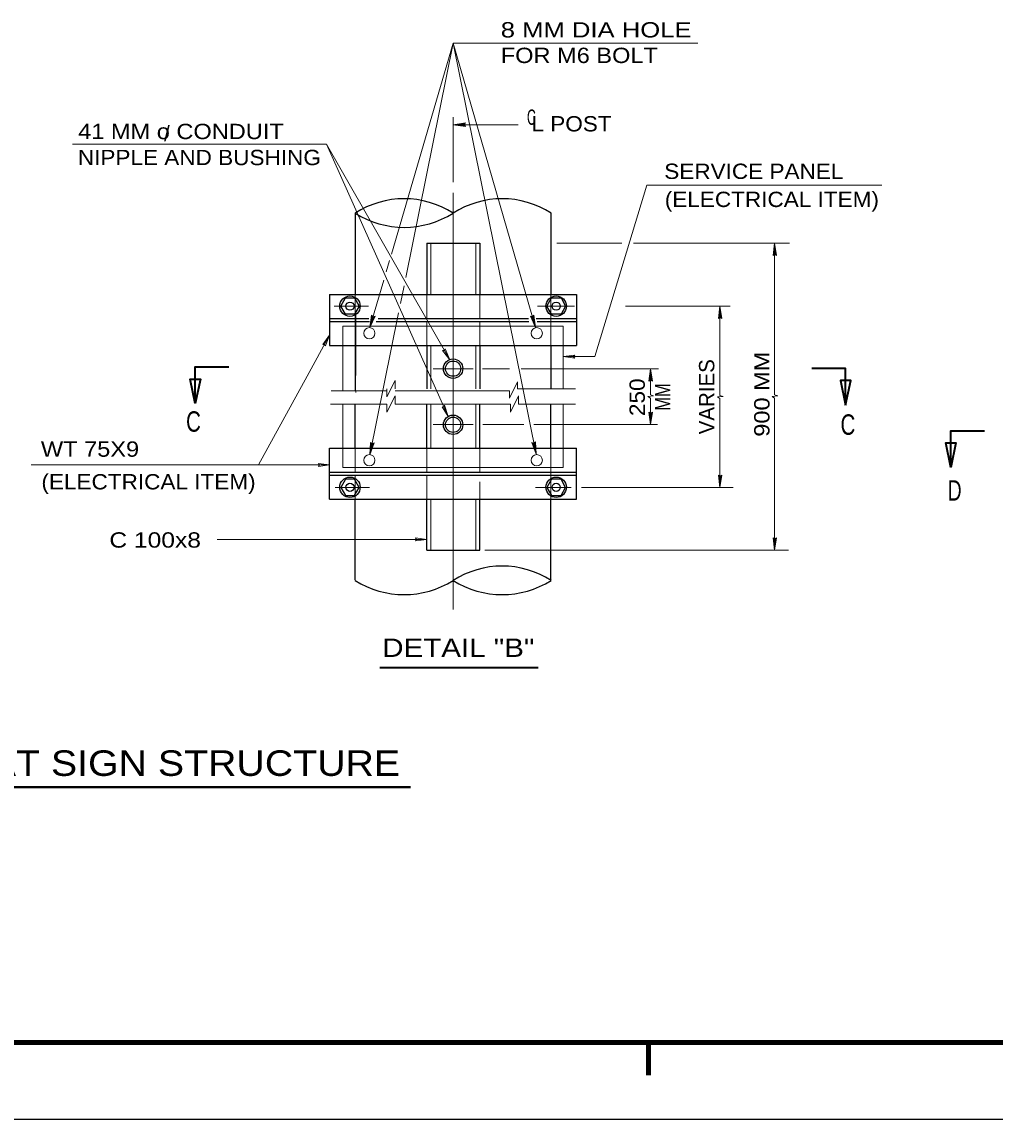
# Model space of a CAD drawing. Extents: x 312601.858 to 312602.699, y 144420.109 to 144420.704.
# Drawn here: x 312602.1557 to 312602.3461, y 144420.1095 to 144420.3243 of the extents above; entities that cross this region are included whole.
import ezdxf
from ezdxf.enums import TextEntityAlignment as Align

# ---------------------------------------------------------------- set-up
doc = ezdxf.new("R2010")
doc.units = 0
doc.header["$LTSCALE"] = 0.0012
doc.linetypes.add('LONG_DASH_SHORT_DASH', pattern=[9.9, 6, -1.2, 1.5, -1.2])
doc.linetypes.add('LONG_DASHED', pattern=[7.5, 6, -1.5])
for name, color, linetype, lineweight in [('1', 7, 'Continuous', 25), ('2', 7, 'Continuous', 25), ('39', 7, 'Continuous', 13)]:
    doc.layers.add(name, color=color, linetype=linetype, lineweight=lineweight)

msp = doc.modelspace()

# ---------------------------------------------------------------- hatches: boundary and pattern name
at = {"layer": '39'}
for points in [[(312602.2423, 144420.3042), (312602.2425, 144420.3039), (312602.2401, 144420.3042), (312602.2425, 144420.3046)], [(312602.303, 144420.2788), (312602.3027, 144420.2786), (312602.303, 144420.281), (312602.3034, 144420.2786)], [(312602.2923, 144420.2665), (312602.292, 144420.2663), (312602.2923, 144420.2687), (312602.2927, 144420.2663)], [(312602.2244, 144420.2666), (312602.2248, 144420.2667), (312602.2238, 144420.2645), (312602.2241, 144420.2669)], [(312602.2556, 144420.2666), (312602.2559, 144420.2669), (312602.2562, 144420.2645), (312602.2552, 144420.2667)], [(312602.2787, 144420.2542), (312602.2784, 144420.254), (312602.2787, 144420.2564), (312602.2791, 144420.254)], [(312602.2787, 144420.2477), (312602.2791, 144420.2479), (312602.2787, 144420.2455), (312602.2784, 144420.2479)], [(312602.2242, 144420.2417), (312602.2246, 144420.2419), (312602.2238, 144420.2396), (312602.2239, 144420.242)], [(312602.2559, 144420.2418), (312602.2562, 144420.2421), (312602.2563, 144420.2397), (312602.2555, 144420.242)], [(312602.2923, 144420.2354), (312602.2927, 144420.2356), (312602.2923, 144420.2332), (312602.292, 144420.2356)], [(312602.303, 144420.2231), (312602.3034, 144420.2233), (312602.303, 144420.2209), (312602.3027, 144420.2233)]]:
    msp.add_hatch(color=256, dxfattribs=at).paths.add_polyline_path(points)

# ---------------------------------------------------------------- linework, layer by layer
at = {"layer": '1', "lineweight": 13}
for p, q in [((312602.2401, 144420.3202), (312602.288, 144420.3202)), ((312602.2401, 144420.293), (312602.2401, 144420.3057)), ((312602.2401, 144420.3042), (312602.2528, 144420.3042)), ((312602.1656, 144420.3004), (312602.2153, 144420.3004)), ((312602.214, 144420.3004), (312602.2149, 144420.3004)), ((312602.2153, 144420.3004), (312602.2391, 144420.2471)), ((312602.2153, 144420.3004), (312602.2394, 144420.2582)), ((312602.2678, 144420.2588), (312602.278, 144420.2924)), ((312602.278, 144420.2924), (312602.2781, 144420.2924)), ((312602.2781, 144420.2924), (312602.324, 144420.2924)), ((312602.2731, 144420.281), (312602.2604, 144420.281)), ((312602.2781, 144420.281), (312602.2754, 144420.281)), ((312602.3059, 144420.281), (312602.2781, 144420.281)), ((312602.303, 144420.281), (312602.303, 144420.2513)), ((312602.2738, 144420.2687), (312602.2943, 144420.2687)), ((312602.2923, 144420.2687), (312602.2923, 144420.2512)), ((312602.2159, 144420.263), (312602.2115, 144420.255)), ((312602.2616, 144420.2588), (312602.2678, 144420.2588)), ((312602.2511, 144420.2564), (312602.2458, 144420.2564)), ((312602.2803, 144420.2564), (312602.2534, 144420.2564)), ((312602.2787, 144420.2564), (312602.2787, 144420.2513)), ((312602.2115, 144420.255), (312602.202, 144420.2376)), ((312602.2271, 144420.2509), (312602.2287, 144420.2541)), ((312602.2287, 144420.2525), (312602.2287, 144420.2541)), ((312602.2511, 144420.2507), (312602.2527, 144420.2539)), ((312602.2527, 144420.2525), (312602.2527, 144420.2539)), ((312602.2162, 144420.2521), (312602.2271, 144420.2521)), ((312602.2271, 144420.2509), (312602.2271, 144420.2525)), ((312602.2271, 144420.2479), (312602.2287, 144420.2511)), ((312602.2287, 144420.2521), (312602.2511, 144420.2521)), ((312602.2287, 144420.2495), (312602.2287, 144420.2511)), ((312602.2511, 144420.2507), (312602.2511, 144420.2521)), ((312602.2513, 144420.2479), (312602.2529, 144420.2511)), ((312602.2527, 144420.2525), (312602.264, 144420.2525)), ((312602.2529, 144420.2495), (312602.2529, 144420.2511)), ((312602.2161, 144420.2495), (312602.2271, 144420.2495)), ((312602.2271, 144420.2479), (312602.2271, 144420.2495)), ((312602.2287, 144420.2495), (312602.2513, 144420.2495)), ((312602.2513, 144420.2479), (312602.2513, 144420.2495)), ((312602.2529, 144420.2495), (312602.264, 144420.2495)), ((312602.2787, 144420.2507), (312602.2787, 144420.2455)), ((312602.2923, 144420.2506), (312602.2923, 144420.2332)), ((312602.303, 144420.2507), (312602.303, 144420.2209)), ((312602.2539, 144420.2455), (312602.2459, 144420.2455)), ((312602.2801, 144420.2455), (312602.2559, 144420.2455)), ((312602.2159, 144420.2376), (312602.1575, 144420.2376)), ((312602.2949, 144420.2332), (312602.2652, 144420.2332)), ((312602.2115, 144420.223), (312602.1939, 144420.223)), ((312602.2349, 144420.223), (312602.2115, 144420.223))]:
    msp.add_line(p, q, dxfattribs=at)
at = {"layer": '1', "linetype": 'LONG_DASH_SHORT_DASH', "lineweight": 13}
for p, q in [((312602.2401, 144420.2093), (312602.2401, 144420.2909)), ((312602.2168, 144420.2687), (312602.2235, 144420.2687)), ((312602.2566, 144420.2687), (312602.2638, 144420.2687)), ((312602.2362, 144420.2564), (312602.244, 144420.2564)), ((312602.2362, 144420.2455), (312602.244, 144420.2455)), ((312602.217, 144420.2332), (312602.2237, 144420.2332)), ((312602.2562, 144420.2332), (312602.2632, 144420.2332))]:
    msp.add_line(p, q, dxfattribs=at)
at = {"layer": '1'}
for p, q in [((312602.2209, 144420.2869), (312602.2209, 144420.271)), ((312602.2592, 144420.2869), (312602.2592, 144420.271)), ((312602.2349, 144420.281), (312602.2453, 144420.281)), ((312602.2349, 144420.281), (312602.2349, 144420.271)), ((312602.2453, 144420.281), (312602.2453, 144420.271)), ((312602.2159, 144420.271), (312602.2159, 144420.261)), ((312602.2159, 144420.2663), (312602.2236, 144420.2663)), ((312602.2254, 144420.2663), (312602.2548, 144420.2663)), ((312602.2563, 144420.2663), (312602.2642, 144420.2663)), ((312602.2159, 144420.2657), (312602.2237, 144420.2657)), ((312602.225, 144420.2657), (312602.2549, 144420.2657)), ((312602.2565, 144420.2657), (312602.2642, 144420.2657)), ((312602.2159, 144420.261), (312602.2642, 144420.261)), ((312602.2209, 144420.261), (312602.2209, 144420.2521)), ((312602.2349, 144420.261), (312602.2349, 144420.2525)), ((312602.2453, 144420.261), (312602.2453, 144420.2525)), ((312602.2592, 144420.261), (312602.2592, 144420.2525)), ((312602.2209, 144420.2409), (312602.2209, 144420.2495)), ((312602.2349, 144420.2409), (312602.2349, 144420.2495)), ((312602.2453, 144420.2409), (312602.2453, 144420.2495)), ((312602.2592, 144420.2409), (312602.2592, 144420.2495)), ((312602.2159, 144420.2409), (312602.2642, 144420.2409)), ((312602.2159, 144420.2309), (312602.2159, 144420.2409)), ((312602.2159, 144420.2362), (312602.2642, 144420.2362)), ((312602.2159, 144420.2356), (312602.2642, 144420.2356)), ((312602.2209, 144420.215), (312602.2209, 144420.2309)), ((312602.2349, 144420.2209), (312602.2349, 144420.2309)), ((312602.2453, 144420.2209), (312602.2453, 144420.2309)), ((312602.2592, 144420.215), (312602.2592, 144420.2309)), ((312602.2349, 144420.2209), (312602.2453, 144420.2209))]:
    msp.add_line(p, q, dxfattribs=at)
at = {"layer": '1', "linetype": 'LONG_DASHED', "lineweight": 13}
for p, q in [((312602.2357, 144420.281), (312602.2357, 144420.271)), ((312602.2445, 144420.281), (312602.2445, 144420.271)), ((312602.2209, 144420.271), (312602.2209, 144420.261)), ((312602.2349, 144420.271), (312602.2349, 144420.2663)), ((312602.2453, 144420.271), (312602.2453, 144420.2663)), ((312602.2592, 144420.271), (312602.2592, 144420.261)), ((312602.221, 144420.2674), (312602.221, 144420.2551)), ((312602.2185, 144420.2648), (312602.2616, 144420.2648)), ((312602.2185, 144420.2648), (312602.2185, 144420.2521)), ((312602.2349, 144420.2657), (312602.2349, 144420.261)), ((312602.2453, 144420.2657), (312602.2453, 144420.261)), ((312602.2616, 144420.2648), (312602.2616, 144420.2525)), ((312602.2357, 144420.261), (312602.2357, 144420.2525)), ((312602.2445, 144420.261), (312602.2445, 144420.2525)), ((312602.221, 144420.2518), (312602.221, 144420.2521)), ((312602.2185, 144420.2495), (312602.2185, 144420.2371)), ((312602.2357, 144420.2409), (312602.2357, 144420.2495)), ((312602.2445, 144420.2409), (312602.2445, 144420.2495)), ((312602.2616, 144420.2371), (312602.2616, 144420.2495)), ((312602.2209, 144420.2362), (312602.2209, 144420.2409)), ((312602.2349, 144420.2362), (312602.2349, 144420.2409)), ((312602.2453, 144420.2363), (312602.2453, 144420.2409)), ((312602.2592, 144420.2309), (312602.2592, 144420.2409)), ((312602.2185, 144420.2371), (312602.2616, 144420.2371)), ((312602.2209, 144420.2309), (312602.2209, 144420.2356)), ((312602.2349, 144420.2309), (312602.2349, 144420.2356)), ((312602.2453, 144420.2309), (312602.2453, 144420.2343)), ((312602.2357, 144420.2209), (312602.2357, 144420.2309)), ((312602.2445, 144420.2209), (312602.2445, 144420.2309))]:
    msp.add_line(p, q, dxfattribs=at)
at = {"layer": '1', "lineweight": 35}
msp.add_line((312602.2257, 144420.1979), (312602.2567, 144420.1979), dxfattribs=at)
at = {"layer": '1', "lineweight": 40}
msp.add_line((312602.0221, 144420.1745), (312602.2317, 144420.1745), dxfattribs=at)
at = {"layer": '1'}
for points in [[(312602.2159, 144420.271), (312602.2642, 144420.271), (312602.2642, 144420.261)], [(312602.2159, 144420.2309), (312602.2642, 144420.2309), (312602.2642, 144420.2409)]]:
    msp.add_lwpolyline(points, dxfattribs=at)
for points in [[(312602.2217, 144420.2687), (312602.2208, 144420.2671), (312602.219, 144420.2671), (312602.2181, 144420.2687), (312602.219, 144420.2703), (312602.2208, 144420.2703)], [(312602.2621, 144420.2687), (312602.2612, 144420.2671), (312602.2593, 144420.2671), (312602.2584, 144420.2687), (312602.2593, 144420.2703), (312602.2612, 144420.2703)], [(312602.2217, 144420.2332), (312602.2208, 144420.2348), (312602.219, 144420.2348), (312602.2181, 144420.2332), (312602.219, 144420.2316), (312602.2208, 144420.2316)], [(312602.2621, 144420.2332), (312602.2612, 144420.2348), (312602.2593, 144420.2348), (312602.2584, 144420.2332), (312602.2593, 144420.2316), (312602.2612, 144420.2316)]]:
    msp.add_lwpolyline(points, close=True, dxfattribs=at)
at = {"layer": '1', "lineweight": 13}
for points in [[(312602.2146, 144420.2612), (312602.2159, 144420.263), (312602.2151, 144420.2609), (312602.2149, 144420.2612)], [(312602.2385, 144420.2603), (312602.2394, 144420.2582), (312602.238, 144420.26), (312602.2384, 144420.26)], [(312602.2639, 144420.2585), (312602.2616, 144420.2588), (312602.2639, 144420.2591), (312602.2636, 144420.2588)], [(312602.2384, 144420.2493), (312602.2391, 144420.2471), (312602.2379, 144420.249), (312602.2383, 144420.2489)], [(312602.2137, 144420.2379), (312602.2159, 144420.2376), (312602.2137, 144420.2373), (312602.2139, 144420.2376)], [(312602.2327, 144420.2233), (312602.2349, 144420.223), (312602.2327, 144420.2227), (312602.2329, 144420.223)]]:
    msp.add_lwpolyline(points, close=True, dxfattribs=at)
msp.add_lwpolyline([(312602.3057, 144420.2209), (312602.2781, 144420.2209), (312602.2463, 144420.2209)], dxfattribs=at)
at = {"layer": '1'}
for centre, radius in [((312602.219885, 144420.268687), 0.001998), ((312602.260248, 144420.268687), 0.001998), ((312602.219885, 144420.268687), 0.000799), ((312602.260248, 144420.268687), 0.000799), ((312602.240067, 144420.256448), 0.001898), ((312602.240067, 144420.256448), 0.001499), ((312602.240067, 144420.245459), 0.001898), ((312602.240067, 144420.245459), 0.001499), ((312602.219885, 144420.23322), 0.001998), ((312602.219885, 144420.23322), 0.000799), ((312602.260248, 144420.23322), 0.001998), ((312602.260248, 144420.23322), 0.000799)]:
    msp.add_circle(centre, radius, dxfattribs=at)
at = {"layer": '1', "lineweight": 13}
for centre in [(312602.223682, 144420.263392), (312602.256451, 144420.263392), (312602.223682, 144420.238515), (312602.256451, 144420.238515)]:
    msp.add_circle(centre, 0.001099, dxfattribs=at)
at = {"layer": '1'}
for centre, start, end in [((312602.230476, 144420.271877), 57.47959, 122.52041), ((312602.249658, 144420.271877), 57.47959, 122.52041), ((312602.230476, 144420.301963), 237.47959, 302.52041), ((312602.249658, 144420.199944), 57.47959, 122.52041), ((312602.230476, 144420.23003), 237.47959, 302.52041), ((312602.249658, 144420.23003), 237.47959, 302.52041)]:
    msp.add_arc(centre, 0.01784, start, end, dxfattribs=at)
at = {"layer": '2', "lineweight": 13}
for p, q in [((312602.228, 144420.2789), (312602.2401, 144420.3202)), ((312602.2401, 144420.3202), (312602.2308, 144420.2743)), ((312602.2563, 144420.2397), (312602.2401, 144420.3202)), ((312602.2401, 144420.3202), (312602.2562, 144420.2645)), ((312602.227, 144420.2754), (312602.2276, 144420.2776)), ((312602.2238, 144420.2645), (312602.2265, 144420.2738)), ((312602.2305, 144420.2727), (312602.2298, 144420.2692)), ((312602.2294, 144420.2674), (312602.2238, 144420.2396))]:
    msp.add_line(p, q, dxfattribs=at)
for points in [[(312602.2787, 144420.2507), (312602.2782, 144420.251), (312602.2793, 144420.2511), (312602.2787, 144420.2513)], [(312602.2923, 144420.2506), (312602.2918, 144420.2509), (312602.2929, 144420.251), (312602.2923, 144420.2512)], [(312602.303, 144420.2507), (312602.3025, 144420.251), (312602.3036, 144420.2511), (312602.303, 144420.2513)]]:
    msp.add_lwpolyline(points, dxfattribs=at)
at = {"layer": '39', "lineweight": 158}
for p, q in [((312601.9088, 144420.1245), (312602.6838, 144420.1245)), ((312602.2783, 144420.1181), (312602.2783, 144420.1245))]:
    msp.add_line(p, q, dxfattribs=at)
at = {"layer": '39', "lineweight": 25}
msp.add_line((312601.8578, 144420.1095), (312602.6988, 144420.1095), dxfattribs=at)
at = {"layer": '39'}
for points in [[(312602.2423, 144420.3042), (312602.2425, 144420.3039), (312602.2401, 144420.3042), (312602.2425, 144420.3046)], [(312602.303, 144420.2788), (312602.3027, 144420.2786), (312602.303, 144420.281), (312602.3034, 144420.2786)], [(312602.2923, 144420.2665), (312602.292, 144420.2663), (312602.2923, 144420.2687), (312602.2927, 144420.2663)], [(312602.2244, 144420.2666), (312602.2248, 144420.2667), (312602.2238, 144420.2645), (312602.2241, 144420.2669)], [(312602.2556, 144420.2666), (312602.2559, 144420.2669), (312602.2562, 144420.2645), (312602.2552, 144420.2667)], [(312602.2787, 144420.2542), (312602.2784, 144420.254), (312602.2787, 144420.2564), (312602.2791, 144420.254)], [(312602.1906, 144420.2544), (312602.1896, 144420.2496), (312602.1886, 144420.2544)], [(312602.3159, 144420.2541), (312602.3169, 144420.2493), (312602.3179, 144420.2541)], [(312602.2787, 144420.2477), (312602.2791, 144420.2479), (312602.2787, 144420.2455), (312602.2784, 144420.2479)], [(312602.2242, 144420.2417), (312602.2246, 144420.2419), (312602.2238, 144420.2396), (312602.2239, 144420.242)], [(312602.2559, 144420.2418), (312602.2562, 144420.2421), (312602.2563, 144420.2397), (312602.2555, 144420.242)], [(312602.3385, 144420.2419), (312602.3375, 144420.2371), (312602.3365, 144420.2419)], [(312602.2923, 144420.2354), (312602.2927, 144420.2356), (312602.2923, 144420.2332), (312602.292, 144420.2356)], [(312602.303, 144420.2231), (312602.3034, 144420.2233), (312602.303, 144420.2209), (312602.3027, 144420.2233)]]:
    msp.add_lwpolyline(points, close=True, dxfattribs=at)
at = {"layer": '39', "lineweight": 35}
for points in [[(312602.1896, 144420.2498), (312602.1896, 144420.2568), (312602.1962, 144420.2568)], [(312602.3169, 144420.2495), (312602.3169, 144420.2565), (312602.3103, 144420.2565)], [(312602.3375, 144420.2373), (312602.3375, 144420.2443), (312602.3441, 144420.2443)]]:
    msp.add_lwpolyline(points, dxfattribs=at)
for points in [[(312602.1896, 144420.2496), (312602.1886, 144420.2544), (312602.1906, 144420.2544)], [(312602.3169, 144420.2493), (312602.3179, 144420.2541), (312602.3159, 144420.2541)], [(312602.3375, 144420.2371), (312602.3365, 144420.2419), (312602.3385, 144420.2419)]]:
    msp.add_lwpolyline(points, close=True, dxfattribs=at)

# ---------------------------------------------------------------- texts
at = {"layer": '1'}
for s, height, width, p in [('8 MM DIA HOLE ', 0.003, 1.25, (312602.2494, 144420.3213)), ('FOR M6 BOLT', 0.003, 1.15, (312602.2494, 144420.3163)), ('SERVICE PANEL', 0.003, 1.1, (312602.2814, 144420.2936)), ('(ELECTRICAL ITEM)', 0.003, 1.1, (312602.2815, 144420.2881)), ('C', 0.004, 0.75, (312602.1878, 144420.2441)), ('C', 0.004, 0.75, (312602.3159, 144420.2435)), ('D', 0.004, 0.7, (312602.3369, 144420.2306)), ('DETAIL "B"', 0.0036, 1.2, (312602.2262, 144420.2))]:
    msp.add_text(s, height=height, dxfattribs=dict(at, width=width)).set_placement(p)
for s, width, p in [('41 MM o CONDUIT', 1.15, (312602.1868, 144420.3014)), ('NIPPLE AND BUSHING', 1.1, (312602.1904, 144420.2963)), ('(ELECTRICAL ITEM)', 1.1, (312602.18045, 144420.2328))]:
    msp.add_text(s, height=0.003, dxfattribs=dict(at, width=width)).set_placement(p, align=Align.CENTER)
msp.add_text('VARIES', height=0.003, rotation=90, dxfattribs=at).set_placement((312602.2912, 144420.25095), align=Align.CENTER)
at = {"layer": '2'}
for s, height, width, p in [('C', 0.003, 0.6, (312602.2554, 144420.3042)), ('L POST', 0.003, 1.1, (312602.26325, 144420.3029)), ('WT 75X9', 0.003, 1.15, (312602.169, 144420.2392)), ('C 100x8', 0.003, 1.2, (312602.18175, 144420.2214)), ('TYPICAL SERVICE PANEL DETAIL AT SIGN STRUCTURE', 0.005, 1.15, (312602.1263, 144420.1767))]:
    msp.add_text(s, height=height, dxfattribs=dict(at, width=width)).set_placement(p, align=Align.CENTER)
msp.add_text('/', height=0.003, dxfattribs=at).set_placement((312602.18405, 144420.301), align=Align.CENTER)
for s, width, p in [('900 MM', 1.15, (312602.302, 144420.25145)), ('250', 1.1, (312602.2776, 144420.25085)), ('MM', 0.8, (312602.2826, 144420.2509))]:
    msp.add_text(s, height=0.003, rotation=90, dxfattribs=dict(at, width=width)).set_placement(p, align=Align.CENTER)

doc.saveas('drawing.dxf')
